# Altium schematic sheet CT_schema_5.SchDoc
size 405 x 321 mm
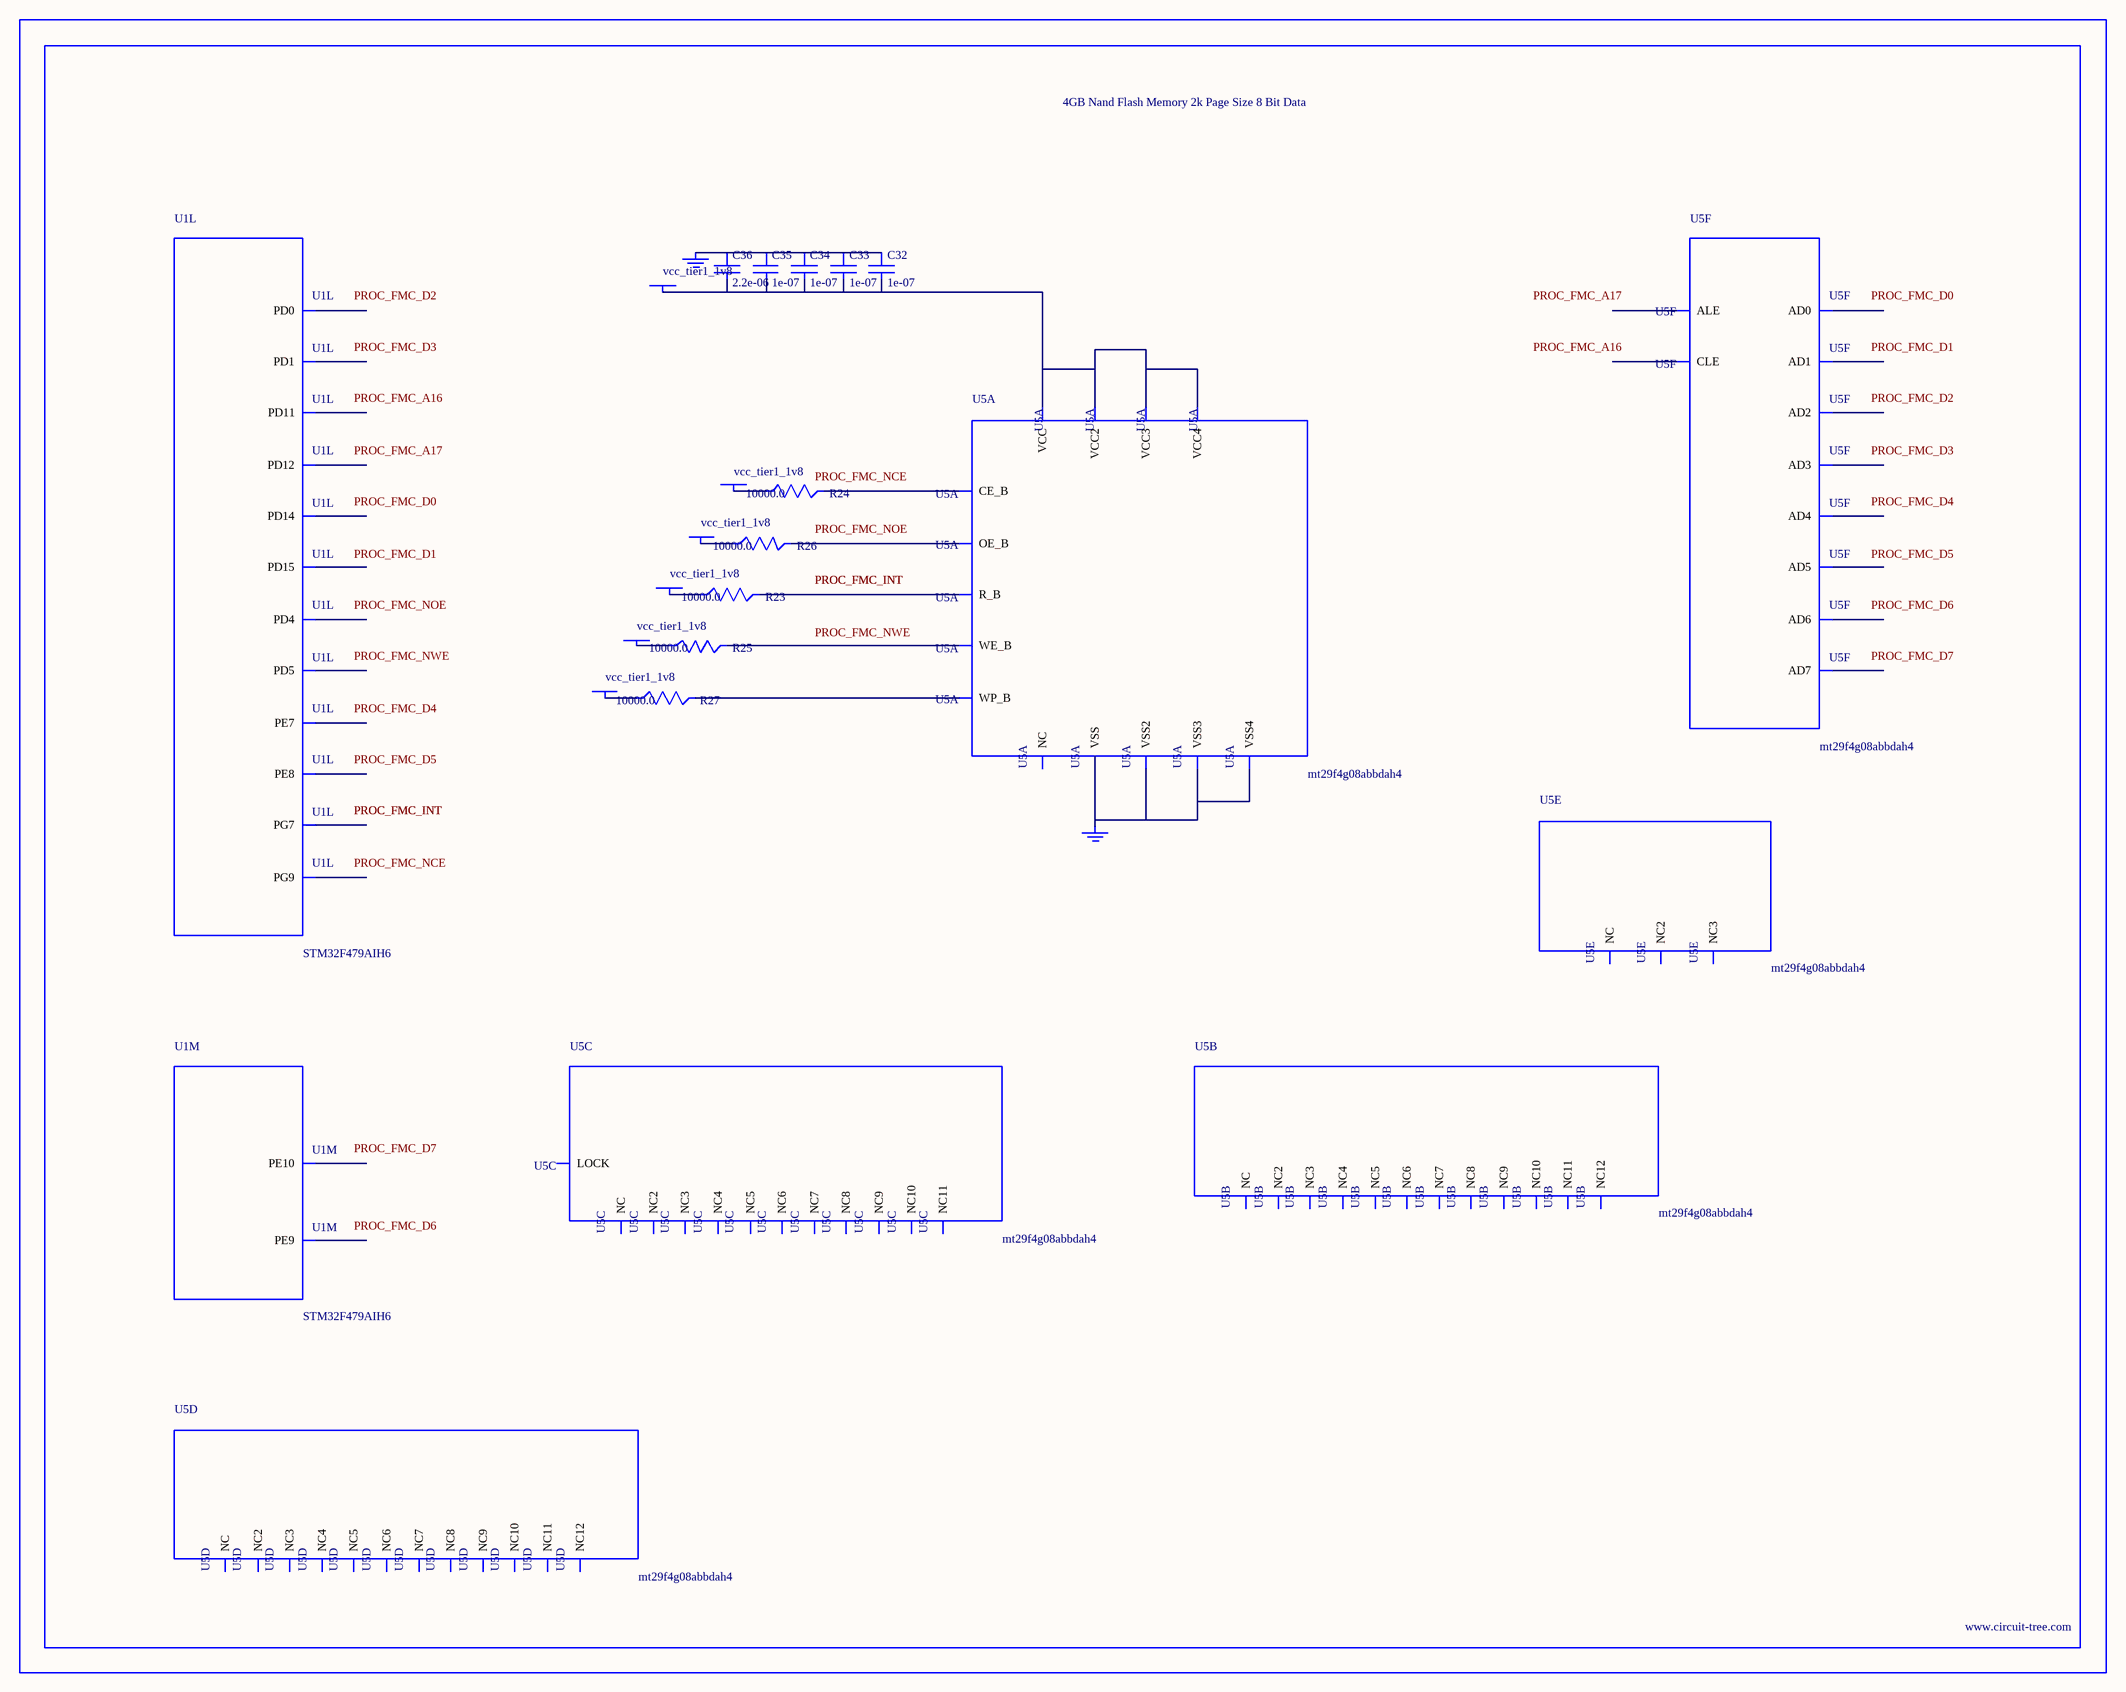
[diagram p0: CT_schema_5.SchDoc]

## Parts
BORDER4  (no value)
C32  1e-07  [C0402]
C33  1e-07  [C0402]
C34  1e-07  [C0402]
C35  1e-07  [C0402]
C36  2.2e-06  [C0603]
GND_INSTANCE_4_0  (no value)
GND_INSTANCE_4_1  (no value)
POWER_INSTANCE_4_0  vcc_tier1_1v8
POWER_INSTANCE_4_1  vcc_tier1_1v8
POWER_INSTANCE_4_2  vcc_tier1_1v8
POWER_INSTANCE_4_3  vcc_tier1_1v8
POWER_INSTANCE_4_4  vcc_tier1_1v8
POWER_INSTANCE_4_5  vcc_tier1_1v8
R23  10000.0  [R0603]
R24  10000.0  [R0603]
R25  10000.0  [R0603]
R26  10000.0  [R0603]
R27  10000.0  [R0603]
U1  STM32F479AIH6  [UFBGA169]  (parts L,M of 14)
U5  mt29f4g08abbdah4  [VFBGA-63]  (parts A,B,C,D,E,F of 6)

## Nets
NetC32_1: C32.1 C33.1 C34.1 C35.1 C36.1 GND_INSTANCE_4_0.0(GND)
NetC32_2: C32.2 C33.2 C34.2 C35.2 C36.2 POWER_INSTANCE_4_0.0(PWR) U5.D3(VCC) U5.G4(VCC2) U5.H8(VCC3) U5.J6(VCC4)
NetGND_INSTANCE_4_1_0: GND_INSTANCE_4_1.0(GND) U5.C5(VSS) U5.F7(VSS2) U5.K3(VSS3) U5.K8(VSS4)
NetPOWER_INSTANCE_4_1_0: POWER_INSTANCE_4_1.0(PWR) R23.1
NetPOWER_INSTANCE_4_2_0: POWER_INSTANCE_4_2.0(PWR) R24.1
NetPOWER_INSTANCE_4_3_0: POWER_INSTANCE_4_3.0(PWR) R25.1
NetPOWER_INSTANCE_4_4_0: POWER_INSTANCE_4_4.0(PWR) R26.1
NetPOWER_INSTANCE_4_5_0: POWER_INSTANCE_4_5.0(PWR) R27.1
NetR23_2: R23.2 U5.C8(R_B)
NetR24_2: R24.2 U5.C6(CE_B)
NetR25_2: R25.2 U5.C7(WE_B)
NetR26_2: R26.2 U5.D4(OE_B)
NetR27_2: R27.2 U5.C3(WP_B)

Not connected (* = marked no-connect by the designer): U1 B7(PD5) C6(PD4) C7(PD1) C9(PD0) E6(PG9) E11(PG7) G6(PE8) H6(PE9) H7(PE10) L12(PD14) L13(PD15) M11(PD11) M13(PD12) N7(PE7); U5 A1(NC) A2(NC3) A9(NC4) A10(NC2) B1(NC5) B9(NC7) B10(NC6) C4(ALE) D5(CLE) D6(NC8) D7(NC9) D8(NC10) E3(NC11) E4(NC12) E5(NC) E6(NC2) E7(NC3) E8(NC4) F3(NC5) F4(NC6) F5(NC7) F6(NC8) F8(NC9) G3(NC) G5(LOCK) G6(NC10) G7(NC11) G8(NC) H3(NC2) H4(AD0) H5(NC3) H6(NC4) H7(NC5) J3(NC6) J4(AD1) J5(NC7) J7(AD5) J8(AD7) K4(AD2) K5(AD3) K6(AD4) K7(AD6) L1(NC8) L2(NC10) L9(NC11) L10(NC9) M1(NC12) M2(NC2) M9(NC3) M10(NC)

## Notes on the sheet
- Labels drawn without touching a wire or pin: PROC_FMC_A16, PROC_FMC_A17, PROC_FMC_D0, PROC_FMC_D1, PROC_FMC_D2, PROC_FMC_D3, PROC_FMC_D4, PROC_FMC_D5, PROC_FMC_D6, PROC_FMC_D7, PROC_FMC_NCE, PROC_FMC_NOE, PROC_FMC_NWE

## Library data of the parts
BORDER4 = BORDER_PAGE4
C32-C35 = C0402C104K3RACTU
C36 = C0603C225K8RACTU
GND_INSTANCE_4_0 GND_INSTANCE_4_1 = GND
POWER_INSTANCE_4_0-POWER_INSTANCE_4_5 = PWR
R23-R27 = RC0603JR-0710KL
